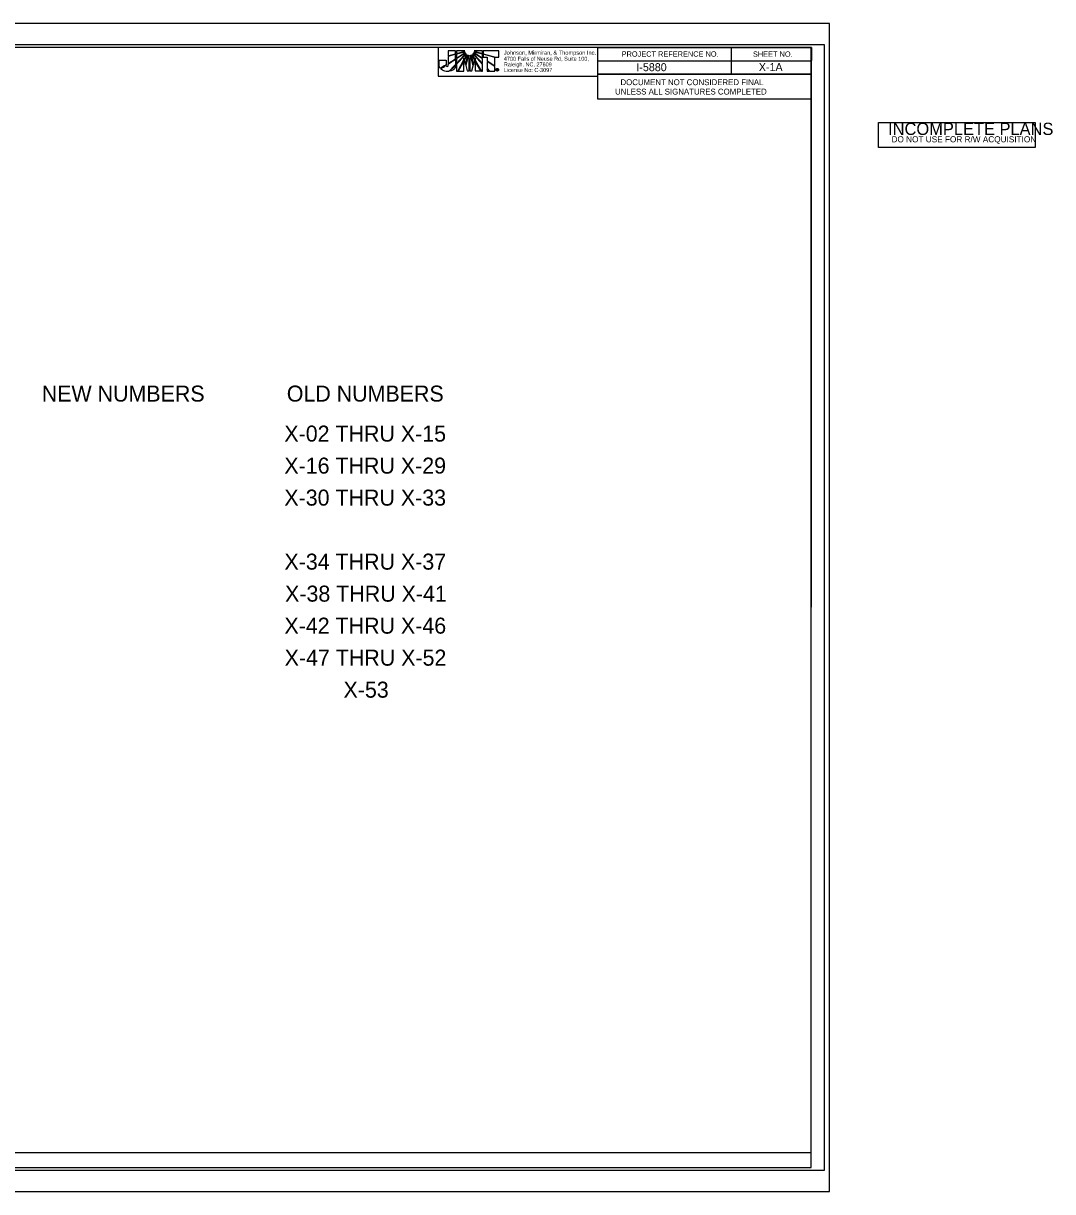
# Model space of a CAD drawing. Extents: x 2862872 to 2864765, y 971793 to 972888.
# Drawn here: x 2863800 to 2864765, y 971793 to 972888 of the extents above; entities that cross this region are included whole.
import ezdxf

# ---------------------------------------------------------------- set-up
doc = ezdxf.new("R2010")
doc.units = 0
for name, color, linetype in [('Prop Dimension Text', 7, 'Continuous'), ('Scratch_Level_0', 7, 'Continuous'), ('Sheet Cutting Line CELL', 7, 'Continuous'), ('Sheet Data Field CELL', 7, 'Continuous'), ('Sheet Plan CELL', 7, 'Continuous'), ('Sheet Plot Border Inside CELL', 7, 'Continuous'), ('Sheet Plot Border Outside CELL', 7, 'Continuous'), ('Sheet Sticker Exception Certification CELL', 7, 'Continuous'), ('Sheet Sticker Incomplete CELL', 7, 'Continuous'), ('Sheet XS Number', 7, 'Continuous')]:
    doc.layers.add(name, color=color, linetype=linetype)

msp = doc.modelspace()

# ---------------------------------------------------------------- linework, layer by layer
at = {"layer": 'Prop Dimension Text'}
for p, q in [((2864205.2, 972862.5), (2864198.2, 972862.5)), ((2864198.2, 972862.5), (2864198.2, 972857.9)), ((2864198.2, 972857.9), (2864205.2, 972859.8)), ((2864205.2, 972859.3), (2864198.2, 972857.3)), ((2864198.2, 972857.3), (2864198.2, 972850.8)), ((2864198.2, 972850.8), (2864205.2, 972855.2)), ((2864205.2, 972859.8), (2864205.2, 972862.5)), ((2864205.2, 972855.2), (2864205.2, 972859.3)), ((2864213.8, 972862.6), (2864205.9, 972862.6)), ((2864205.9, 972862.6), (2864205.9, 972860.1)), ((2864205.9, 972860.1), (2864211.8, 972861.7)), ((2864211.8, 972861.1), (2864205.9, 972859.5)), ((2864205.9, 972859.5), (2864205.9, 972855.7)), ((2864205.9, 972855.7), (2864211.2, 972859.1)), ((2864212, 972859), (2864205.9, 972855.1)), ((2864205.9, 972850.7), (2864213.3, 972858.4)), ((2864213.6, 972858), (2864205.9, 972850)), ((2864205.9, 972855.1), (2864205.9, 972850.7)), ((2864207.1, 972843.6), (2864212.8, 972854)), ((2864212.8, 972853), (2864207.6, 972843.6)), ((2864211.2, 972859.1), (2864214.1, 972861.4)), ((2864211.8, 972861.7), (2864213.8, 972862.6)), ((2864214.1, 972861.4), (2864211.8, 972861.1)), ((2864214.7, 972860.3), (2864212, 972859)), ((2864212.8, 972854), (2864212.8, 972855.8)), ((2864212.8, 972855.8), (2864213.1, 972854.6)), ((2864212.9, 972843.6), (2864212.8, 972853)), ((2864213.1, 972854.6), (2864214.6, 972857.2)), ((2864213.3, 972858.4), (2864214.7, 972860.3)), ((2864215.1, 972857.1), (2864213.3, 972853.9)), ((2864213.3, 972853.9), (2864214.5, 972849.7)), ((2864215.5, 972859.5), (2864213.6, 972858)), ((2864214.5, 972849.7), (2864216.3, 972856.7)), ((2864214.6, 972857.2), (2864215.5, 972859.5)), ((2864216.7, 972856.3), (2864214.7, 972848.7)), ((2864216.5, 972858.9), (2864215.1, 972857.1)), ((2864216.3, 972856.7), (2864216.5, 972858.9)), ((2864217.6, 972858.5), (2864216.7, 972856.3)), ((2864217.9, 972853), (2864217.6, 972858.5)), ((2864218, 972843.7), (2864217.9, 972853)), ((2864218.8, 972858.5), (2864218.4, 972853)), ((2864218.4, 972853), (2864218.5, 972843.7)), ((2864219.7, 972856.3), (2864218.8, 972858.5)), ((2864221.7, 972848.6), (2864219.7, 972856.3)), ((2864219.9, 972858.9), (2864220.2, 972856.6)), ((2864221.3, 972857.1), (2864219.9, 972858.9)), ((2864220.2, 972856.6), (2864222, 972849.5)), ((2864220.9, 972859.5), (2864221.8, 972857.2)), ((2864222.8, 972858.1), (2864220.9, 972859.5)), ((2864223.1, 972853.8), (2864221.3, 972857.1)), ((2864221.7, 972860.3), (2864223.1, 972858.4)), ((2864224.4, 972859), (2864221.7, 972860.3)), ((2864221.8, 972857.2), (2864223.3, 972854.5)), ((2864222, 972849.5), (2864223.1, 972853.8)), ((2864222.3, 972861.4), (2864225.3, 972859)), ((2864224.5, 972861.1), (2864222.3, 972861.4)), ((2864230.5, 972862.6), (2864222.7, 972862.6)), ((2864222.7, 972862.6), (2864224.7, 972861.7)), ((2864230.5, 972849.9), (2864222.8, 972858.1)), ((2864223.1, 972858.4), (2864230.5, 972850.7)), ((2864223.3, 972854.5), (2864223.6, 972855.8)), ((2864223.6, 972855.8), (2864223.6, 972853.8)), ((2864223.6, 972853.8), (2864229.3, 972843.6)), ((2864228.7, 972843.7), (2864223.6, 972852.8)), ((2864223.6, 972852.8), (2864223.6, 972843.7)), ((2864230.5, 972855.2), (2864224.4, 972859)), ((2864230.5, 972859.5), (2864224.5, 972861.1)), ((2864224.7, 972861.7), (2864230.5, 972860)), ((2864225.3, 972859), (2864230.5, 972855.8)), ((2864230.5, 972860), (2864230.5, 972862.6)), ((2864230.5, 972855.8), (2864230.5, 972859.5)), ((2864230.5, 972850.7), (2864230.5, 972855.2)), ((2864245.8, 972862.6), (2864231.1, 972862.6)), ((2864231.1, 972862.6), (2864231.1, 972859.9)), ((2864231.1, 972859.9), (2864231.1, 972859.8)), ((2864231.1, 972859.8), (2864242.7, 972856.6)), ((2864231.1, 972859.4), (2864231.1, 972859.3)), ((2864241.9, 972856.3), (2864231.1, 972859.4)), ((2864231.1, 972859.3), (2864231.1, 972856.5)), ((2864231.1, 972856.5), (2864234.7, 972856.5)), ((2864234.7, 972856.5), (2864234.7, 972853.1)), ((2864234.7, 972853.1), (2864241.9, 972848.5)), ((2864241.9, 972848.5), (2864241.9, 972856.3)), ((2864242.7, 972856.6), (2864245.8, 972856.6)), ((2864245.8, 972856.6), (2864245.8, 972862.6)), ((2864205.9, 972850), (2864205.9, 972843.6)), ((2864205.9, 972843.6), (2864207.1, 972843.6)), ((2864207.6, 972843.6), (2864212.9, 972843.6)), ((2864214.7, 972848.7), (2864216, 972843.7)), ((2864216, 972843.7), (2864218, 972843.7)), ((2864218.5, 972843.7), (2864220.4, 972843.7)), ((2864220.4, 972843.7), (2864221.7, 972848.6)), ((2864223.6, 972843.7), (2864228.7, 972843.7)), ((2864229.3, 972843.6), (2864230.5, 972843.6)), ((2864230.5, 972843.6), (2864230.5, 972849.9)), ((2864234.7, 972852.6), (2864234.7, 972846.3)), ((2864241.9, 972848), (2864234.7, 972852.6)), ((2864234.7, 972846.3), (2864237.2, 972843.6)), ((2864236.5, 972843.6), (2864234.7, 972845.6)), ((2864234.7, 972845.6), (2864234.7, 972843.6)), ((2864234.7, 972843.6), (2864236.5, 972843.6)), ((2864237.2, 972843.6), (2864242, 972843.6)), ((2864242, 972843.6), (2864241.9, 972848)), ((2864243.8, 972844.3), (2864243.8, 972845.4)), ((2864243.8, 972845.4), (2864244.2, 972845.4)), ((2864244, 972844.3), (2864243.8, 972844.3)), ((2864244.2, 972845.2), (2864244, 972845.2)), ((2864244, 972845.2), (2864244, 972844.9)), ((2864244, 972844.9), (2864244.2, 972844.9)), ((2864244.2, 972844.7), (2864244, 972844.7)), ((2864244, 972844.7), (2864244, 972844.3)), ((2864244.2, 972846), (2864244.2, 972845.8)), ((2864244.2, 972845.8), (2864244.2, 972846)), ((2864244.2, 972845.4), (2864244.2, 972845.2)), ((2864244.2, 972845.2), (2864244.2, 972845.4)), ((2864244.2, 972845.4), (2864244.3, 972845.4)), ((2864244.3, 972845.2), (2864244.2, 972845.2)), ((2864244.2, 972844.9), (2864244.2, 972844.7)), ((2864244.2, 972844.7), (2864244.2, 972844.9)), ((2864244.2, 972844.9), (2864244.2, 972844.9)), ((2864244.2, 972844.7), (2864244.2, 972844.7)), ((2864244.2, 972843.9), (2864244.2, 972843.7)), ((2864244.2, 972843.7), (2864244.2, 972843.9)), ((2864244.2, 972843.9), (2864244.2, 972843.9)), ((2864244.2, 972843.7), (2864244.2, 972843.7))]:
    msp.add_line(p, q, dxfattribs=at)
msp.add_lwpolyline([(2864188.7, 972838.8), (2864338.6, 972838.8), (2864338.6, 972865.8), (2864188.7, 972865.8)], close=True, dxfattribs=at)
for points in [[(2864198.2, 972857.9), (2864205.2, 972859.8), (2864205.2, 972862.5), (2864198.2, 972862.5), (2864198.2, 972857.9)], [(2864198.2, 972850.8), (2864205.2, 972855.2), (2864205.2, 972859.3), (2864198.2, 972857.3), (2864198.2, 972850.8)], [(2864211.8, 972861.7), (2864213.8, 972862.6), (2864205.9, 972862.6), (2864205.9, 972860.1), (2864211.8, 972861.7)], [(2864205.9, 972859.5), (2864205.9, 972855.7), (2864211.2, 972859.1), (2864214.1, 972861.4), (2864211.8, 972861.1), (2864205.9, 972859.5)], [(2864205.9, 972855.1), (2864205.9, 972850.7), (2864213.3, 972858.4), (2864214.7, 972860.3), (2864212, 972859), (2864205.9, 972855.1)], [(2864215.5, 972859.5), (2864213.6, 972858), (2864205.9, 972850), (2864205.9, 972843.6), (2864207.1, 972843.6), (2864212.8, 972854), (2864212.8, 972855.8), (2864213.1, 972854.6), (2864214.6, 972857.2), (2864215.5, 972859.5)], [(2864207.6, 972843.6), (2864212.9, 972843.6), (2864212.8, 972853), (2864207.6, 972843.6)], [(2864216.5, 972858.9), (2864215.1, 972857.1), (2864213.3, 972853.9), (2864214.5, 972849.7), (2864216.3, 972856.7), (2864216.5, 972858.9)], [(2864216.7, 972856.3), (2864214.7, 972848.7), (2864216, 972843.7), (2864218, 972843.7), (2864217.9, 972853), (2864217.6, 972858.5), (2864216.7, 972856.3)], [(2864218.8, 972858.5), (2864218.4, 972853), (2864218.5, 972843.7), (2864220.4, 972843.7), (2864221.7, 972848.6), (2864219.7, 972856.3), (2864218.8, 972858.5)], [(2864219.9, 972858.9), (2864220.2, 972856.6), (2864222, 972849.5), (2864223.1, 972853.8), (2864221.3, 972857.1), (2864219.9, 972858.9)], [(2864220.9, 972859.5), (2864221.8, 972857.2), (2864223.3, 972854.5), (2864223.6, 972855.8), (2864223.6, 972853.8), (2864229.3, 972843.6), (2864230.5, 972843.6), (2864230.5, 972849.9), (2864222.8, 972858.1), (2864220.9, 972859.5)], [(2864221.7, 972860.3), (2864223.1, 972858.4), (2864230.5, 972850.7), (2864230.5, 972855.2), (2864224.4, 972859), (2864221.7, 972860.3)], [(2864222.3, 972861.4), (2864225.3, 972859), (2864230.5, 972855.8), (2864230.5, 972859.5), (2864224.5, 972861.1), (2864222.3, 972861.4)], [(2864224.7, 972861.7), (2864230.5, 972860), (2864230.5, 972862.6), (2864222.7, 972862.6), (2864224.7, 972861.7)], [(2864223.6, 972843.7), (2864228.7, 972843.7), (2864223.6, 972852.8), (2864223.6, 972843.7)], [(2864245.8, 972862.6), (2864231.1, 972862.6), (2864231.1, 972859.9), (2864231.1, 972859.8), (2864242.7, 972856.6), (2864245.8, 972856.6), (2864245.8, 972862.6)], [(2864231.1, 972859.4), (2864231.1, 972859.3), (2864231.1, 972856.5), (2864234.7, 972856.5), (2864234.7, 972853.1), (2864241.9, 972848.5), (2864241.9, 972856.3), (2864231.1, 972859.4)], [(2864234.7, 972852.6), (2864234.7, 972846.3), (2864237.2, 972843.6), (2864242, 972843.6), (2864241.9, 972848), (2864234.7, 972852.6), (2864234.7, 972852.6)], [(2864234.7, 972843.6), (2864234.7, 972843.6), (2864236.5, 972843.6), (2864234.7, 972845.6), (2864234.7, 972843.6)], [(2864244.7, 972844.6), (2864244.7, 972844.5), (2864244.7, 972844.5), (2864244.7, 972844.4), (2864244.7, 972844.3), (2864244.5, 972844.3)]]:
    msp.add_lwpolyline(points, dxfattribs=at)
for points, degree in [([(2864196.2, 972853.8), (2864196.2, 972853.8), (2864189.7, 972853.8), (2864189.7, 972853.8), (2864189.7, 972853.8), (2864189.7, 972849.7), (2864189.7, 972849.7), (2864189.7, 972849.7), (2864189.7, 972849.3), (2864189.7, 972849.3), (2864189.7, 972848), (2864190.1, 972847), (2864190.8, 972846.2), (2864190.8, 972846.2), (2864196.2, 972849.4), (2864196.2, 972849.5), (2864196.2, 972849.5), (2864196.2, 972853.8), (2864196.2, 972853.8)], 3), ([(2864197.2, 972848), (2864196.8, 972848), (2864196.4, 972848.2), (2864196.2, 972849), (2864196.2, 972849), (2864191.2, 972845.8), (2864191.2, 972845.8), (2864192.8, 972844.2), (2864195.2, 972843.2), (2864197.3, 972843.2), (2864197.9, 972843.2), (2864198.3, 972843.3), (2864198.9, 972843.4), (2864198.9, 972843.4), (2864205.2, 972849.9), (2864205.2, 972849.9), (2864205.2, 972849.9), (2864205.2, 972854.7), (2864205.2, 972854.7), (2864205.2, 972854.7), (2864198.2, 972850.2), (2864198.2, 972850.2), (2864198.2, 972848.4), (2864197.7, 972848), (2864197.2, 972848)], 3), ([(2864197.2, 972848), (2864196.8, 972848), (2864196.4, 972848.2), (2864196.2, 972849), (2864196.2, 972849), (2864191.2, 972845.8), (2864191.2, 972845.8), (2864192.8, 972844.2), (2864195.2, 972843.2), (2864197.3, 972843.2), (2864197.9, 972843.2), (2864198.3, 972843.3), (2864198.9, 972843.4), (2864198.9, 972843.4), (2864205.2, 972849.9), (2864205.2, 972849.9), (2864205.2, 972849.9), (2864205.2, 972854.7), (2864205.2, 972854.7), (2864205.2, 972854.7), (2864198.2, 972850.2), (2864198.2, 972850.2), (2864198.2, 972848.4), (2864197.7, 972848), (2864197.2, 972848)], 3), ([(2864205.2, 972849.2), (2864205.2, 972849.2), (2864199.7, 972843.6), (2864199.7, 972843.6), (2864202.4, 972844.2), (2864205.1, 972846), (2864205.2, 972849.2)], 3), ([(2864244.2, 972843.7), (2864243.9, 972843.7), (2864243.6, 972843.8), (2864243.4, 972844), (2864243.2, 972844.2), (2864243, 972844.5), (2864243, 972844.8), (2864243, 972845.2), (2864243.2, 972845.5), (2864243.4, 972845.7), (2864243.6, 972845.9), (2864243.9, 972846), (2864244.2, 972846)], 3), ([(2864244.2, 972845.8), (2864244, 972845.8), (2864243.7, 972845.7), (2864243.6, 972845.5), (2864243.4, 972845.3), (2864243.3, 972845.1), (2864243.3, 972844.8), (2864243.3, 972844.6), (2864243.4, 972844.4), (2864243.6, 972844.2), (2864243.7, 972844), (2864244, 972843.9), (2864244.2, 972843.9)], 3), ([(2864244.2, 972846), (2864244.6, 972846), (2864244.8, 972845.9), (2864245.1, 972845.7), (2864245.3, 972845.5), (2864245.4, 972845.2), (2864245.4, 972844.8)], 3), ([(2864244.2, 972843.9), (2864244.5, 972843.9), (2864244.7, 972844), (2864244.9, 972844.2), (2864245.1, 972844.4), (2864245.2, 972844.6), (2864245.2, 972844.8), (2864245.2, 972845.1), (2864245.1, 972845.3), (2864244.9, 972845.5), (2864244.7, 972845.7), (2864244.5, 972845.8), (2864244.2, 972845.8)], 3), ([(2864244.2, 972844.9), (2864244.4, 972844.9), (2864244.5, 972845), (2864244.5, 972845.1), (2864244.5, 972845.1), (2864244.4, 972845.2), (2864244.3, 972845.2)], 3), ([(2864245.4, 972844.8), (2864245.4, 972844.5), (2864245.3, 972844.2), (2864245.1, 972844), (2864244.9, 972843.8), (2864244.6, 972843.7), (2864244.2, 972843.7)], 3), ([(2864244.4, 972844.7), (2864244.4, 972844.7), (2864244.3, 972844.7), (2864244.2, 972844.7)], 2), ([(2864244.3, 972845.4), (2864244.6, 972845.4), (2864244.7, 972845.3), (2864244.7, 972845.1), (2864244.7, 972845), (2864244.7, 972844.9), (2864244.6, 972844.8)], 3), ([(2864244.5, 972844.3), (2864244.5, 972844.4), (2864244.5, 972844.4), (2864244.5, 972844.5), (2864244.5, 972844.6), (2864244.5, 972844.7), (2864244.4, 972844.7)], 3), ([(2864244.6, 972844.8), (2864244.7, 972844.8), (2864244.7, 972844.7), (2864244.7, 972844.6)], 2)]:
    msp.add_open_spline(points, degree=degree, dxfattribs=at)
at = {"layer": 'Sheet Cutting Line CELL'}
for p, q in [((2864555.6, 972888.3), (2862872.1, 972888.3)), ((2862872.1, 971793.3), (2864555.6, 971793.3))]:
    msp.add_line(p, q, dxfattribs=at)
at = {"layer": 'Sheet Plan CELL'}
for p, q in [((2864463.6, 972865.8), (2864463.6, 972840.8)), ((2864463.6, 972865.8), (2864463.6, 972840.8)), ((2864338.6, 972853.3), (2864538.6, 972853.3)), ((2864338.6, 972853.3), (2864538.6, 972853.3)), ((2864338.6, 972840.8), (2864538.6, 972840.8)), ((2864338.6, 972840.8), (2864538.6, 972840.8)), ((2864338.6, 972840.8), (2864538.6, 972840.8)), ((2864338.6, 972840.8), (2864538.6, 972840.8))]:
    msp.add_line(p, q, dxfattribs=at)
for points in [[(2864538.7, 972865.8), (2863038.6, 972865.8), (2863038.6, 971815.8), (2864538.6, 971815.8)], [(2864538.7, 972865.8), (2863038.6, 972865.8), (2863038.6, 971815.8), (2864538.6, 971815.8)], [(2864338.6, 972865.8), (2864538.7, 972865.8), (2864538.6, 972840.8), (2864338.6, 972840.8)], [(2864338.6, 972865.8), (2864538.7, 972865.8), (2864538.6, 972840.8), (2864338.6, 972840.8)]]:
    msp.add_lwpolyline(points, close=True, dxfattribs=at)
at = {"layer": 'Sheet Plot Border Inside CELL'}
msp.add_lwpolyline([(2862885.1, 971813.3), (2864551.1, 971813.3), (2864551.1, 972868.3), (2862885.1, 972868.3)], close=True, dxfattribs=at)
at = {"layer": 'Sheet Plot Border Outside CELL'}
msp.add_lwpolyline([(2862872.1, 971793.3), (2864555.6, 971793.3), (2864555.6, 972888.3), (2862872.1, 972888.3)], close=True, dxfattribs=at)
msp.add_lwpolyline([(2862872.1, 971793.3), (2864555.6, 971793.3), (2864555.6, 972888.3), (2862872.1, 972888.3)], close=True, dxfattribs=at)
at = {"layer": 'Sheet Sticker Exception Certification CELL'}
for p, q in [((2864338.6, 972817.3), (2864338.6, 972840.8)), ((2864338.6, 972840.8), (2864538.6, 972840.8)), ((2864538.6, 972840.8), (2864538.6, 972817.3)), ((2864538.6, 972817.3), (2864338.6, 972817.3))]:
    msp.add_line(p, q, dxfattribs=at)
at = {"layer": 'Sheet Sticker Incomplete CELL'}
msp.add_lwpolyline([(2864601.6, 972772), (2864601.6, 972795.5), (2864748.6, 972795.5), (2864748.6, 972772)], close=True, dxfattribs=at)
at = {"layer": 'Sheet XS Number'}
msp.add_lwpolyline([(2863038.6, 971830), (2864538.6, 971830), (2864538.6, 972865.8), (2863038.6, 972865.8)], close=True, dxfattribs=at)

# ---------------------------------------------------------------- texts
at = {"layer": 'Prop Dimension Text'}
for s, height, p in [('Johnson, Mirmiran, & Thompson Inc.', 3.83, (2864250.4, 972858.9)), ('4700 Falls of Neuse Rd, Suite 100, ', 3.721, (2864250.4, 972853.3)), ('Raleigh, NC, 27609', 3.721, (2864250.4, 972848)), ('License No: C-3097', 3.721, (2864250.4, 972842.7))]:
    msp.add_text(s, height=height, rotation=360, dxfattribs=at).set_placement(p)
at = {"layer": 'Scratch_Level_0'}
for s, p in [('NEW NUMBERS', (2863817.2, 972533.8)), ('OLD NUMBERS', (2864046.9, 972533.8)), ('X-02 THRU X-15', (2864044.6, 972496.3)), ('X-16 THRU X-29', (2864044.6, 972466.3)), ('X-30 THRU X-33', (2864044.6, 972436.3)), ('X-34 THRU X-37', (2864044.7, 972376.3)), ('X-38 THRU X-41', (2864045.3, 972346.3)), ('X-42 THRU X-46', (2864044.7, 972316.3)), ('X-47 THRU X-52', (2864044.9, 972286.3)), ('X-53', (2864100.1, 972256.3))]:
    msp.add_text(s, height=15, dxfattribs=at).set_placement(p)
at = {"layer": 'Sheet Data Field CELL'}
for s, p in [('I-5880   ', (2864374.6, 972843.5)), ('X-1A', (2864489.4, 972843.6))]:
    msp.add_text(s, height=7.5, rotation=0, dxfattribs=at).set_placement(p)
at = {"layer": 'Sheet Plan CELL'}
for s, p in [('PROJECT REFERENCE NO.', (2864360.8, 972857.1)), ('PROJECT REFERENCE NO.', (2864360.8, 972857.1)), ('SHEET NO.', (2864483.9, 972857)), ('SHEET NO.', (2864483.9, 972857))]:
    msp.add_text(s, height=5, rotation=0, dxfattribs=at).set_placement(p)
at = {"layer": 'Sheet Sticker Exception Certification CELL'}
for s, p in [('DOCUMENT NOT CONSIDERED FINAL', (2864359.7, 972830.4)), ('UNLESS ALL SIGNATURES COMPLETED', (2864354.6, 972821.6))]:
    msp.add_text(s, height=5.5, dxfattribs=at).set_placement(p)
at = {"layer": 'Sheet Sticker Incomplete CELL'}
for s, height, p in [('INCOMPLETE PLANS', 11.52, (2864610.6, 972783.7)), ('DO NOT USE FOR R/W ACQUISITION', 5.76, (2864613.8, 972776.8))]:
    msp.add_text(s, height=height, dxfattribs=at).set_placement(p)

doc.saveas('drawing.dxf')
